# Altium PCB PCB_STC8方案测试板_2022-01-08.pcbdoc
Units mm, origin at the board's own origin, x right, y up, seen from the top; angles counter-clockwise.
Board outline 98 x 98 mm, 2 copper layers (Top Layer, Bottom Layer); 68 components, 57 nets, 265 pads, 60 vias.
Unrouted connection lines stored in the file: 3.
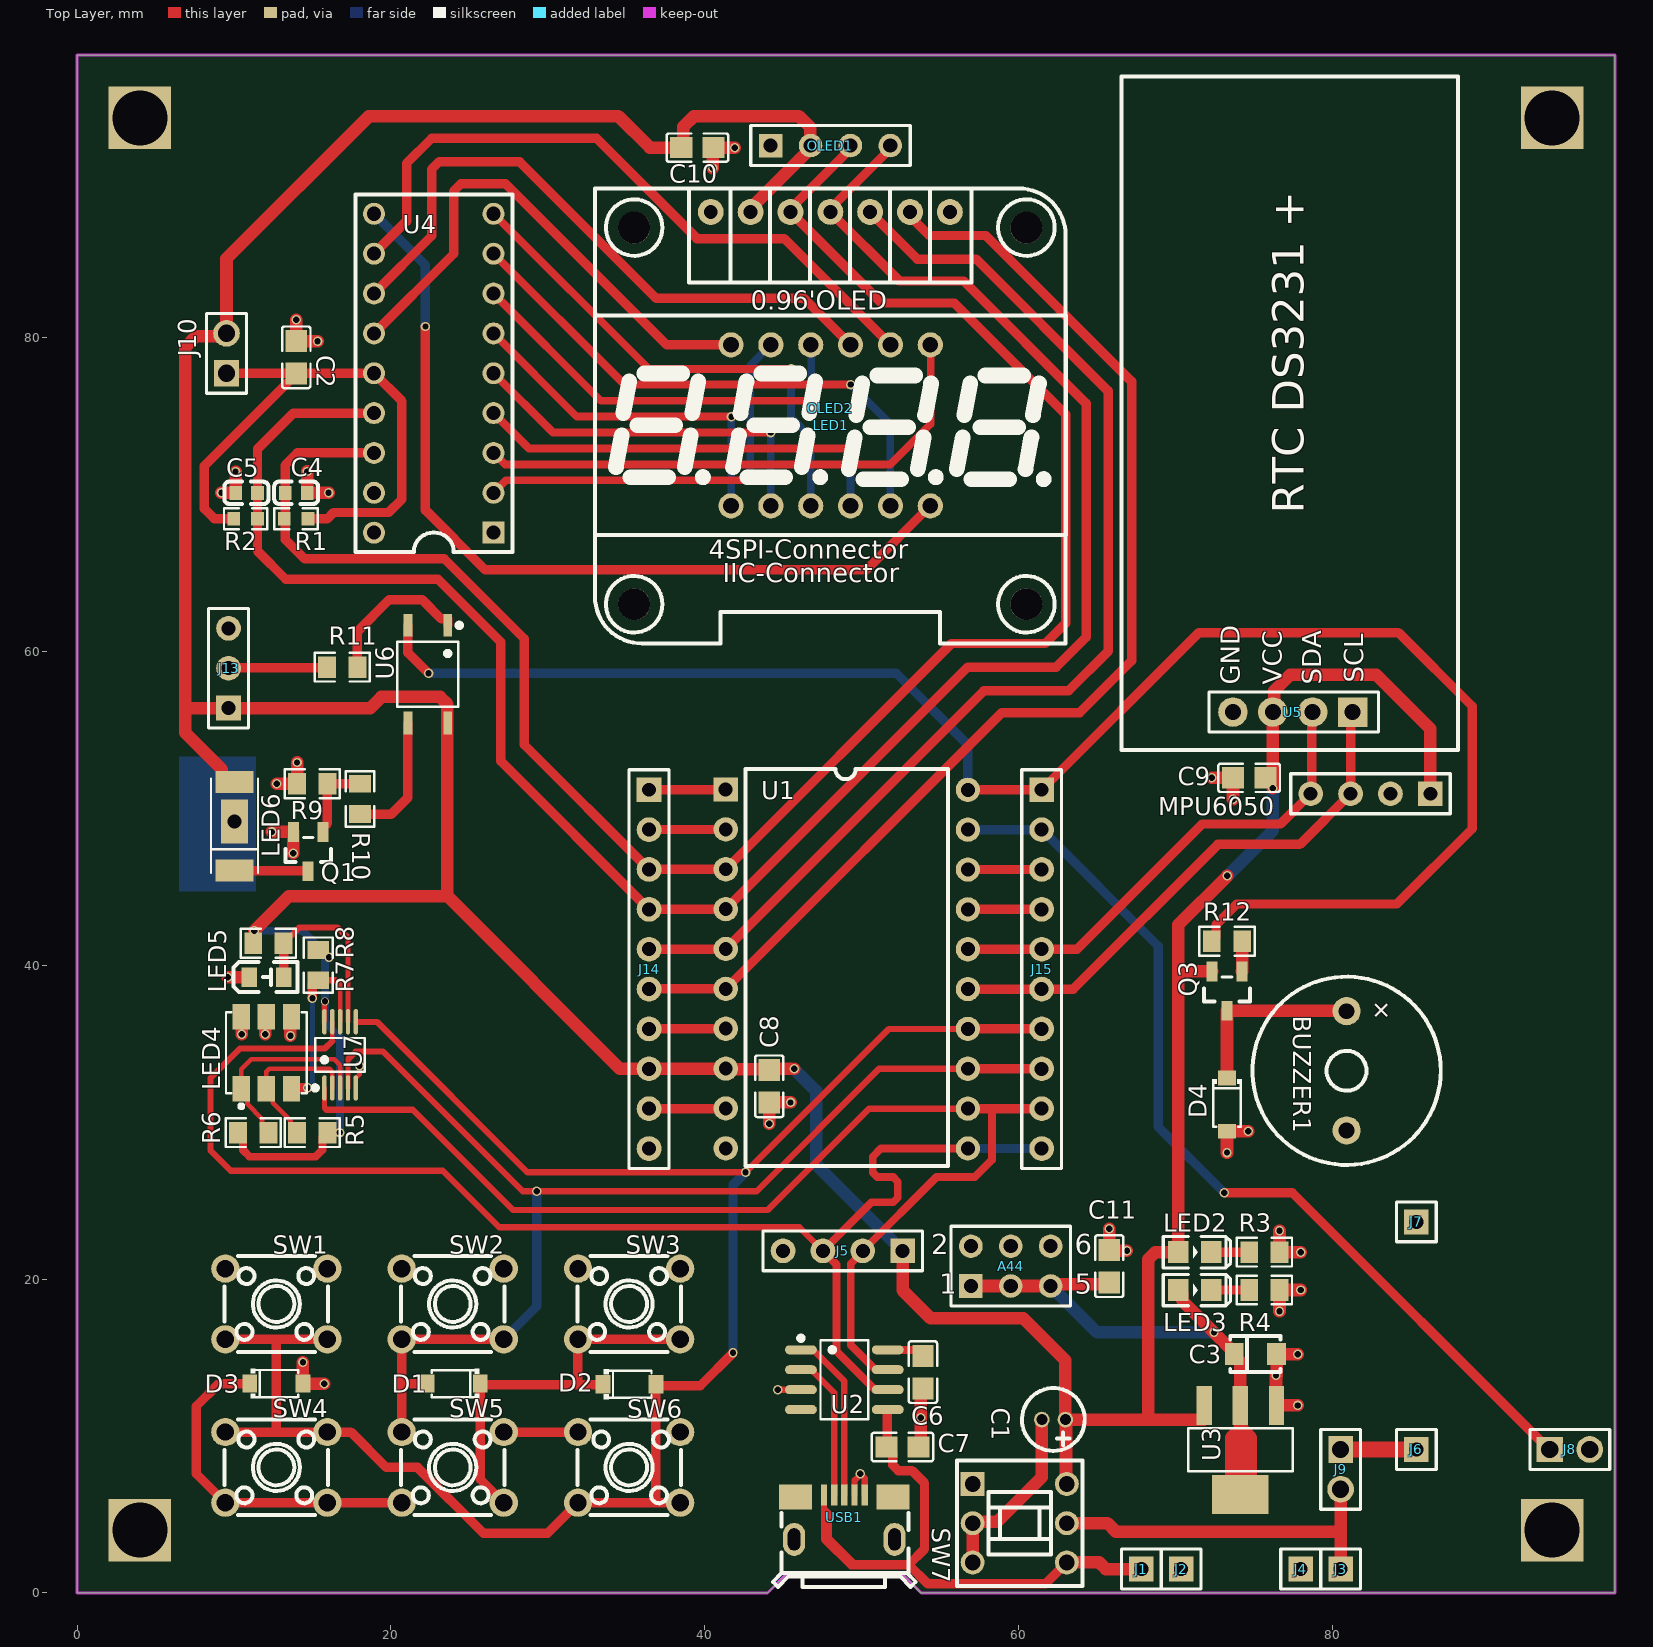
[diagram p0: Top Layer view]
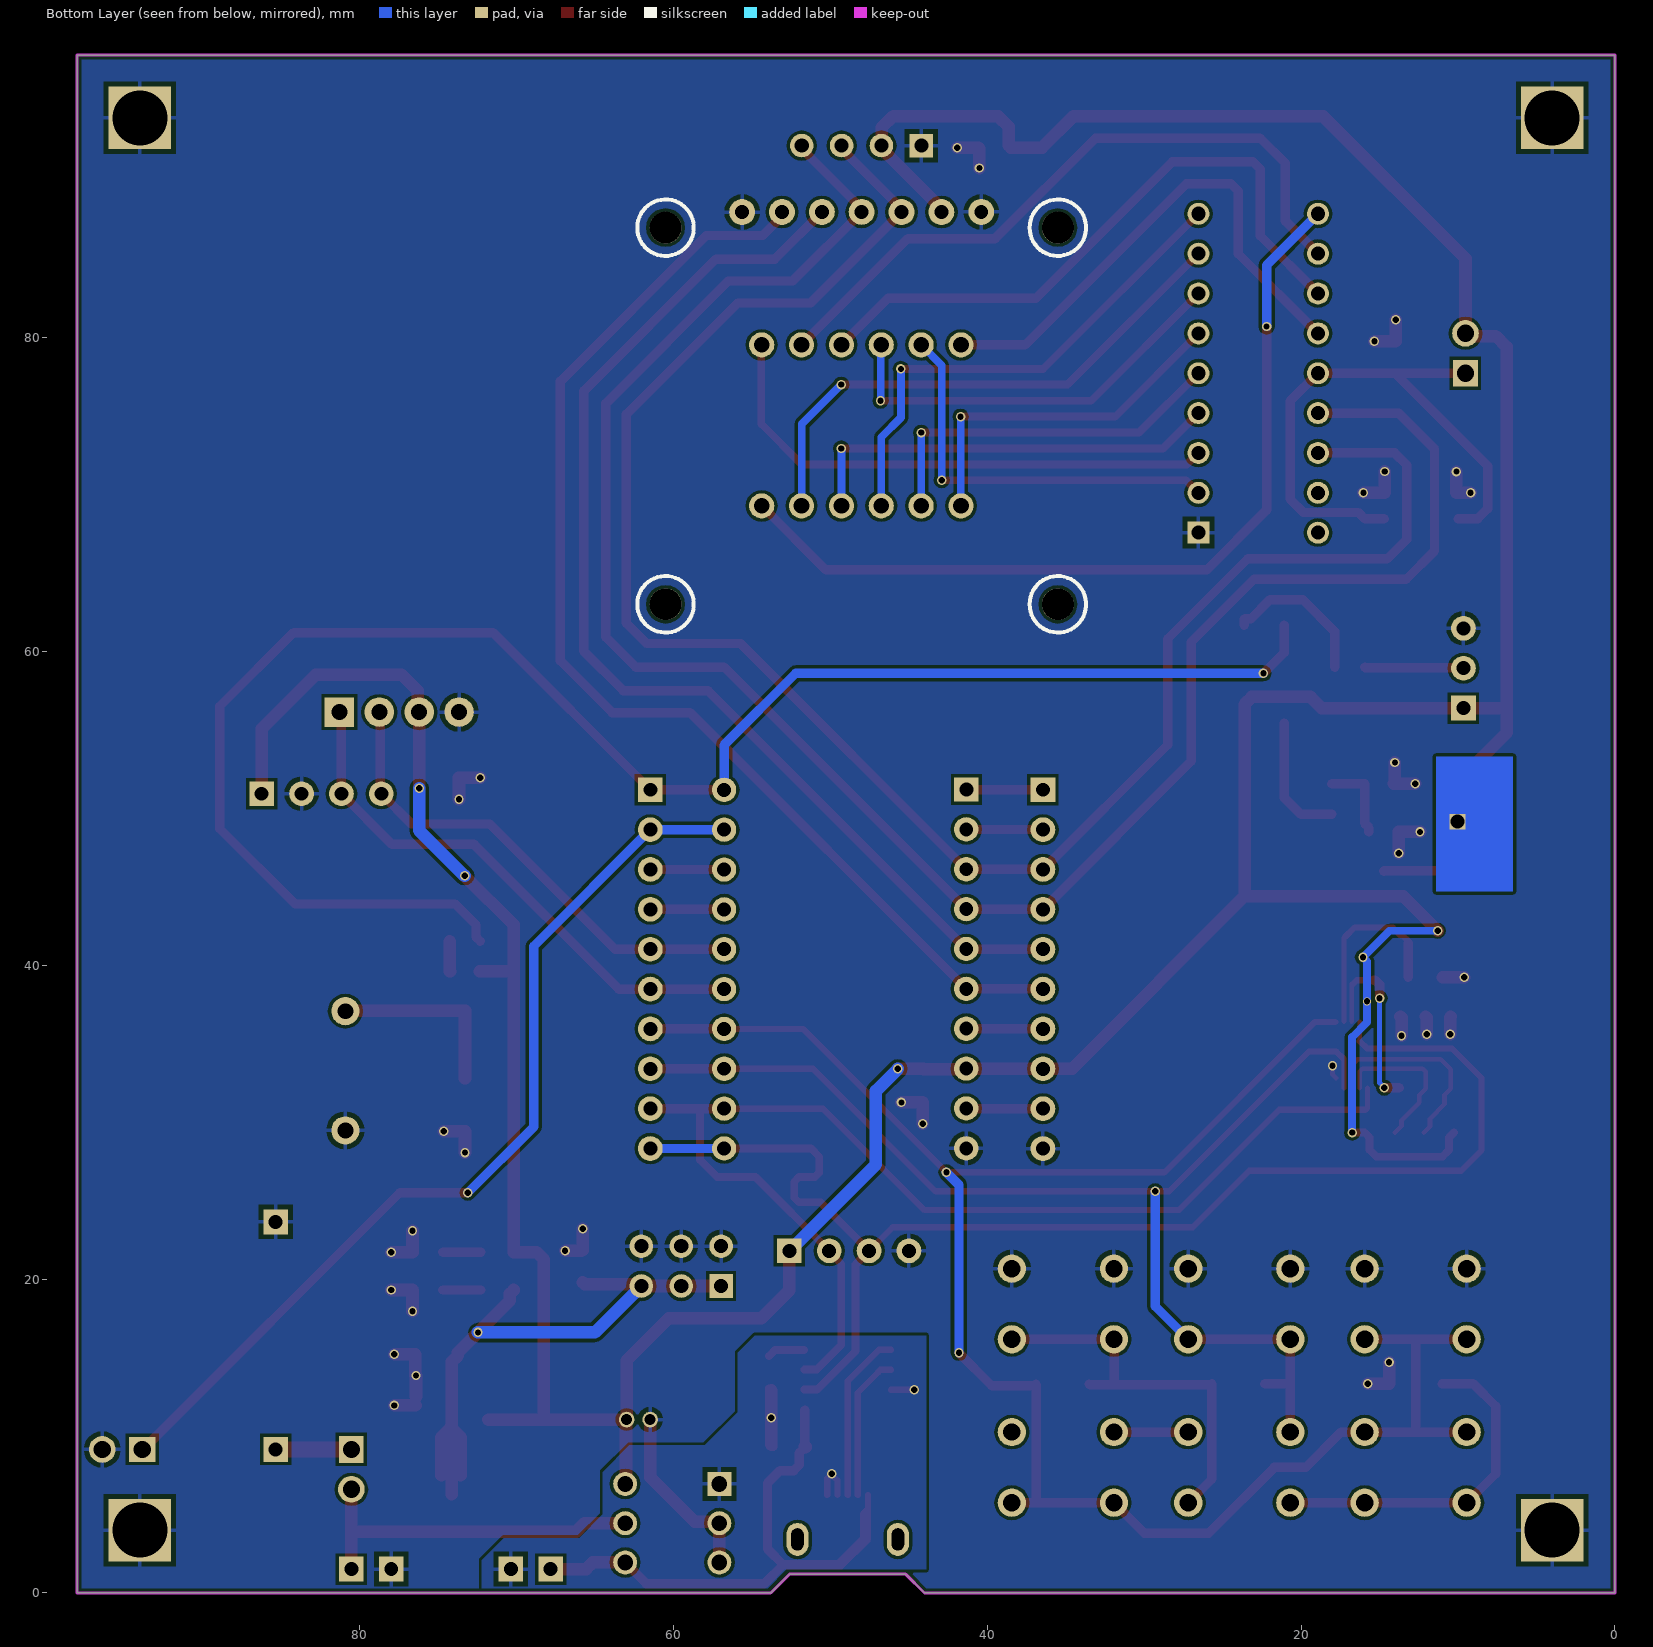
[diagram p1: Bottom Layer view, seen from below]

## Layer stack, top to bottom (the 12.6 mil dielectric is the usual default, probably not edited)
Top Solder: solder mask 0.0102, Solder Resist, Dk 3.5
Top Layer: signal copper 0.0356
Dielectric1: dielectric 0.32, FR-4, Dk 4.8
Bottom Layer: signal copper 0.0356
Bottom Solder: solder mask 0.0102, Solder Resist, Dk 3.5

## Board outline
0,0 0,98 98,98 98,0 53.8,0 52.6,1.2 45.2,1.2 44,0

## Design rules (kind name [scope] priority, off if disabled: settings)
AssemblyTestPointUsage [All] p1 off:
AssemblyTestpoint [All] p1 off: testpointundercomponent=TRUE minsize=1.016 maxsize=2.54 preferedsize=1.524 minholesize=0 maxholesize=1.016 preferedholesize=0.813 testpointgrid=0.025 usegrid=TRUE gridtolerance=0 allowsidetop=TRUE allowsidebottom=TRUE
Clearance [All] p1: gap=0.2 ignorepadtopadclearanceinfootprint=TRUE
ComponentClearance [All] p1 off: gap=0.254 collisioncheckmode=3 verticalgap=0.254 showdistances=FALSE
DiffPairsRouting [All] p1 off: maxlimit=0.254 minlimit=0.254 mostfreqgap=0.254 toplayer_minwidth=0.381 toplayer_maxwidth=0.381 toplayer_prefwidth=0.381 bottomlayer_minwidth=0.381 bottomlayer_maxwidth=0.381 bottomlayer_prefwidth=0.381 maxuncoupledlength=12.7
FabricationTestPointUsage [All] p1 off: valid=0 allowmultiple=FALSE
FabricationTestpoint [All] p1 off: side=3 testpointundercomponent=TRUE minsize=1.016 maxsize=2.54 preferedsize=1.524 minholesize=0 maxholesize=1.016 preferedholesize=0.813 testpointgrid=0.025 allowsidetop=TRUE allowsidebottom=TRUE usegrid=TRUE gridtolerance=0
FanoutControl Fanout_BGA [IsBGA] p1 off: bgadir=Out bgaviamode=Centered fanoutstyle=Auto fanoutdirection=Alternating viagrid=0.025 // Fanout_BGA (Default Rule)
FanoutControl Fanout_LCC [IsLCC] p2 off: bgadir=Out bgaviamode=Centered fanoutstyle=Auto fanoutdirection=Alternating viagrid=0.025 // Fanout_LCC (Default Rule)
FanoutControl Fanout_SOIC [IsSOIC] p3 off: bgadir=Out bgaviamode=Centered fanoutstyle=Auto fanoutdirection=Alternating viagrid=0.025 // Fanout_SOIC (Default Rule)
FanoutControl Fanout_Small [(CompPinCount < 5)] p4 off: bgadir=Out bgaviamode=Centered fanoutstyle=Auto fanoutdirection=OutThenIn viagrid=0.025 // Fanout_Small (Default Rule)
FanoutControl Fanout_Default [All] p5 off: bgadir=Out bgaviamode=Centered fanoutstyle=Auto fanoutdirection=Alternating viagrid=0.025 // Fanout_Default (Default Rule)
Height [All] p1 off: minheight=0 maxheight=25.4 prefheight=12.7
HoleSize [All] p1 off: absolutevalues=TRUE maxlimit=2.54 minlimit=0.025 maxpercent=80.000 minpercent=20.000
HoleToHoleClearance [All] p1 off: gap=0.254 allowstackedmicrovias=TRUE
LayerPairs [All] p1 off: enforce=TRUE
MinimumSolderMaskSliver [All] p1 off: minsoldermaskwidth=0.254
NetAntennae [All] p1 off: netantennaetolerance=0
PasteMaskExpansion [All] p1 off: expansion=0
PlaneClearance [All] p1 off: clearance=0.508
PlaneConnect [All] p1 off: planeconnectstyle=Relief reliefexpansion=0.508 reliefentries=4 reliefconductorwidth=0.254 reliefairgap=0.254
PolygonConnect [All] p1: thpad.connectstyle=Relief thpad.reliefconductorwidth=0.254 thpad.reliefentries=4 thpad.polygonreliefangle="90 Angle" thpad.airgapwidth=0.3 smdpad.connectstyle=Relief smdpad.reliefconductorwidth=0.254 smdpad.reliefentries=4 smdpad.polygonreliefangle="90 Angle" smdpad.airgapwidth=0.3 via.connectstyle=Direct via.reliefconductorwidth=0.254 via.reliefentries=4 via.polygonreliefangle="90 Angle" via.airgapwidth=0.3
RoutingCorners [All] p1 off: cornerstyle=45-Degree minsetback=2.54 maxsetback=2.54
RoutingLayers [All] p1 off: top layer_v5=TRUE bottom layer_v5=TRUE
RoutingPriority [All] p1 off: routingpriority=0
RoutingTopology [All] p1 off: topology=Shortest
RoutingVias [All] p1: holewidth=0.4 width=0.6 viastyle="Through Hole" minholewidth=0.4 minwidth=0.6 maxholewidth=0.4 maxwidth=0.6
ShortCircuit [All] p1 off: allowed=FALSE
SilkToSilkClearance [All] p1 off: silktosilkclearance=0.254
SilkToSolderMaskClearance [IsPad] p1 off: minsilkscreentomaskgap=0.254 clearancetoexposedcopper=TRUE
SolderMaskExpansion [All] p1 off: expansion=0.102 istentingtop=FALSE
UnRoutedNet [All] p1 off:
UnpouredPolygon [All] p1 off:
Width [All] p1: maxlimit=2.54 minlimit=0.254 preferedwidth=0.508
1 further rules are at their usual default settings.

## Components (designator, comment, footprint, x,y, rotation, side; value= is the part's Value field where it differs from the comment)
A44 "Comment" HDR2X3 56.96,19.56 r0 top
BUZZER1 "TMB12A05" BUZ-TH_BD12.0-P7.60-D0.6-FD 80.899,33.274 r270 top
C1 "10u" ?#1 62.23,11.049 r180 top
C2 "104" C0805 13.97,78.74 r270 top
C3 "10uF" CAP-SMD_L3.2-W1.6 75.085,15.216 r0 top
C4 "101" C0603 13.97,70.104 r0 top
C5 "101" C0603 10.8,70.1 r0 top
C6 "104" C0805 53.9,14.07 r270 top
C7 "104" C0805 52.6,9.3 r180 top
C8 "0.1u" C0805 44.109,32.288 r90 top
C9 "0.1u" C0805 74.69,51.943 r0 top
C10 "0.1u" C0805 39.53,92.1 r180 top
C11 "0.1u" C0805 65.775,20.82 r270 top
D1 "1N4148W-T4" SOD-123_L2.8-W1.8-LS3.7-RD 24.003,13.335 r180 top
D2 "1N4148W-T4" SOD-123_L2.8-W1.8-LS3.7-RD 35.2,13.3 r0 top
D3 "1N4148W-T4" SOD-123_L2.8-W1.8-LS3.7-RD 12.7,13.338 r0 top
D4 "1N4148W-T4" SOD-123_L2.8-W1.8-LS3.7-RD 73.279,31.115 r270 top
J1 "充电+" HDR-M-2.54_1X1 67.818,1.524 r270 top
J2 "充电-" HDR-M-2.54_1X1 70.358,1.524 r270 top
J3 "锂电池供电+" HDR-M-2.54_1X1 80.518,1.524 r270 top
J4 "锂电池供电-" HDR-M-2.54_1X1 77.978,1.524 r270 top
J5 "HDR-M-2.54_1x4" HDR-M-2.54_1X4 48.8,21.8 r180 top
J6 "led驱动+" HDR-M-2.54_1X1 85.344,9.144 r90 top
J7 "led驱动-" HDR-M-2.54_1X1 85.344,23.644 r90 top
J8 "PWM输入" HDR-M-2.54_1X2 95.123,9.144 r0 top
J9 "led驱动+" HDR-M-2.54_1X2 80.518,7.874 r270 top
J10 "HDR-M-2.54_1x2" HDR-M-2.54_1X2 9.525,78.994 r90 top
J13 "HDR-M-2.54_1x3" HDR-M-2.54_1X3 9.652,58.928 r90 top
J14 "HDR-M-2.54_1x10" HDR-M-2.54_1X10 36.449,39.751 r270 top
J15 "HDR-M-2.54_1x10" HDR-M-2.54_1X10 61.468,39.751 r270 top
LED1 "SR410361N" LED-SEG-TH_12P-L30.0-W14.0-P2.54-S10.26-BL 48.022,74.404 r0 top
LED2 "LED-0805_G" LED0805_GREEN 71.213,21.717 r0 top
LED3 "LED-0805_G" LED0805_GREEN 71.213,19.304 r0 top
LED4 "5050-RGB" LED-ARRAY-SMD_6P-L5.4-W5.0-TL-FD 12.065,34.417 r90 top
LED5 "0805Y" LED0805-RD_YELLOW 12.065,39.243 r0 top
LED6 "HL-A-5730D34W_C210350" LED-SMD_3P-L5.7-W3.0-RD 10.033,48.849 r90 top
MPU6050 "MCU6050" HDR-M-2.54_1X4 82.423,50.927 r180 top (schematic designator J12)
OLED1 "0.96OLED_4P" HDR1X4 44.2,92.234 r0 top
OLED2 "0.96OLED_7P" 0.96OLED_7P 48,88 r0 top
Q1 "s8050" SOT-23-3_L2.9-W1.3-P1.90-LS2.4-TR 14.732,47.244 r90 top
Q3 "s8550" SOT-23-3_L2.9-W1.6-P1.90-LS2.8-TR-CW 73.279,38.354 r90 top
R1 "10k" R0603 13.961,68.453 r0 top
R2 "10k" R0603 10.747,68.449 r180 top
R3 "1k" R0805 75.658,21.717 r0 top
R4 "680" R0805 75.658,19.304 r0 top
R5 "1k" R0805 14.986,29.337 r180 top
R6 "1k" R0805 11.226,29.337 r180 top
R7 "1k" R0805 15.367,40.005 r90 top
R8 "1k" R0805 12.192,41.402 r180 top
R9 "47k" R0805 14.986,51.562 r0 top
R10 "4k7" R0805 18.034,50.596 r90 top
R11 "1k" R0805 16.9,59 r180 top
R12 "2k" R0805 73.279,41.529 r0 top
SW1 "K2-1102DP-C4SW-04" KEY-TH_4P-L6.0-W6.0-P4.50-LS6.5 12.7,18.415 r0 top
SW2 "K2-1102DP-C4SW-04" KEY-TH_4P-L6.0-W6.0-P4.50-LS6.5 23.939,18.415 r0 top
SW3 "K2-1102DP-C4SW-04" KEY-TH_4P-L6.0-W6.0-P4.50-LS6.5 35.179,18.415 r0 top
SW4 "K2-1102DP-C4SW-04" KEY-TH_4P-L6.0-W6.0-P4.50-LS6.5 12.7,8.001 r0 top
SW5 "K2-1102DP-C4SW-04" KEY-TH_4P-L6.0-W6.0-P4.50-LS6.5 23.939,8.001 r0 top
SW6 "K2-1102DP-C4SW-04" KEY-TH_4P-L6.0-W6.0-P4.50-LS6.5 35.179,8.001 r180 top
SW7 "电源开关" SW-TH_6P-L8.0-W8.0-P2.50 60.071,4.445 r270 top
U1 "STC8G1K17-38I-TSSOP20" DIP-20-wide 41.332,51.199 r0 top
U2 "CH340N" SOP-8_L5.0-W4.0-P1.27-LS6.0-BL 48.895,13.589 r270 top
U3 "AMS1117-3.3" SOT-223-4_L6.5-W3.5-P2.30-LS7.0-BR 74.131,9.117 r90 top
U4 "TM1636" DIP18-2.54-22.8X7.62MM 22.733,77.724 r90 top
U5 "DS3231模块" ?#2 76.962,73.914 r90 top
U6 "TLP184(GB-TPL,SE(T" SOP-4_L3.7-W4.6-P2.54-LS7.0-BR 22.352,58.547 r90 top
U7 "CH442E" MSOP-10_L3.0-W3.0-P0.50-LS5.0-BL 16.764,34.29 r0 top
USB1 "U254-051T-4BH82-S2S" MICRO-USB-SMD_U254-051T-4BH82-S2S 48.895,4.826 r0 top

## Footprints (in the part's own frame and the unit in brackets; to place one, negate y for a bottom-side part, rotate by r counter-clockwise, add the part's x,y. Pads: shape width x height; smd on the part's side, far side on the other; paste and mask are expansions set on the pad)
0.96OLED_7P [mm]
  round 1.65 hole 0.89: 1(-7.619,0.001) 2(-5.079,-0.004) 3(-2.539,-0.004) 4(0.001,0.004) 5(2.539,-0.001) 6(5.079,-0.001) 7(7.619,-0.004)
  round 2.032 hole 2.032 unplated: ""(-12.501,-24.997) ""(-12.501,-0.997) ""(12.498,-24.997) ""(12.498,-0.997)
  silkscreen extent -15,-27.5 15,1.5
BUZ-TH_BD12.0-P7.60-D0.6-FD [mm]
  round 1.8 hole 1: 1(-3.8,0) 2(3.8,0)
  silkscreen extent -6,-6 6,6
C0603 [mm]
  rect 0.8x0.9 smd: 1(-0.7,0) 2(0.7,0)
  silkscreen extent -1.41,-0.71 1.39,0.72
C0805 [mm]
  rect 1.41x1.35 smd: 1(-1.03,0) 2(1.03,0)
  silkscreen extent -1.96,-0.9 1.96,0.9
CAP-SMD_L3.2-W1.6 [mm]
  rect 1.2x1.4 smd: 1(-1.35,0) 2(1.35,0)
  silkscreen extent -1.6,-1.14 1.6,1.14
DIP18-2.54-22.8X7.62MM [mm]
  rect 1.4x1.4 hole 0.899: 1(-10.16,-3.81)
  round 1.4 hole 0.899: 2(-7.62,-3.81) 3(-5.08,-3.81) 4(-2.54,-3.81) 5(0,-3.81) 6(2.54,-3.81) 7(5.08,-3.81) 8(7.62,-3.81) 9(10.16,-3.81) 10(10.16,3.81) 11(7.62,3.81) 12(5.08,3.81) 13(2.54,3.81) 14(0,3.81) 15(-2.54,3.81) 16(-5.08,3.81) 17(-7.62,3.81) 18(-10.16,3.81)
  silkscreen extent -11.38,-5 11.38,5
DIP-20-wide [mil] "STC8G1K17-38I-TSSOP20"
  rect 61x61 hole 35: 1(0,0)
  round 61 hole 35: 2(0.25,-100.02) 3(0.25,-200.04) 4(0.25,-300.06) 5(0.25,-400.08) 6(0.25,-500.1) 7(0.25,-600.12) 8(0.25,-700.14) 9(0.25,-800.16) 10(0.25,-900.18) 11(607.75,-900.59) 12(607.75,-800.62) 13(607.75,-700.64) 14(607.75,-600.66) 15(607.75,-500.68) 16(607.75,-400.7) 17(607.75,-300.73) 18(607.75,-200.75) 19(607.75,-100.77) 20(607.75,-0.79)
  silkscreen extent 50,-945 558,51
HDR1X4 [mm] "Connector; Header; 4 Position"
  rect 1.5x1.5 hole 0.9: 1(0,0)
  round 1.5 hole 0.9: 2(2.54,0) 3(5.08,0) 4(7.62,0)
  silkscreen extent -1.27,-1.27 8.89,1.27
HDR2X3 [mm] "Connector; Header; 3x2 Position"
  rect 1.5x1.5 hole 0.9: 1(0,0)
  round 1.5 hole 0.9: 2(0,2.54) 3(2.54,0) 4(2.54,2.54) 5(5.08,0) 6(5.08,2.54)
  silkscreen extent -1.27,-1.27 6.35,3.81, body extent -1.27,-1.27 6.35,3.81, height 8.54
HDR-M-2.54_1X1 [mil]
  rect 62x62 hole 35: 1(0,0)
  silkscreen extent -50,-50 50,50
HDR-M-2.54_1X2 [mm]
  rect 1.7x1.575 hole 1.1: 1(-1.27,0)
  round 1.7 hole 1.1: 2(1.27,0)
  silkscreen extent -2.54,-1.27 2.54,1.27
HDR-M-2.54_1X3 [mil]
  rect 62x62 hole 35: 1(-100,0)
  round 62 hole 35: 2(0,0) 3(100,0)
  silkscreen extent -150,-50 150,50
HDR-M-2.54_1X4 [mil]
  rect 62x62 hole 35: 1(-150,0)
  round 62 hole 35: 2(-50,0) 3(50,0) 4(150,0)
  silkscreen extent -200,-50 200,50
HDR-M-2.54_1X10 [mil]
  rect 62x62 hole 35: 1(-450,0)
  round 62 hole 35: 2(-350,0) 3(-250,0) 4(-150,0) 5(-50,0) 6(50,0) 7(150,0) 8(250,0) 9(350,0) 10(450,0)
  silkscreen extent -500,-50 500,50
KEY-TH_4P-L6.0-W6.0-P4.50-LS6.5 [mm]
  round 1.8 hole 1.1: 1(-3.251,-2.25) 2(3.251,-2.25) 3(3.251,2.25) 4(-3.251,2.25)
  silkscreen extent -3.3,-3.05 3.3,3.05
LED0805-RD_YELLOW [mm]
  rect 1x1.25 smd: 1(-1.1,0) 2(1.1,0)
  silkscreen extent -2.1,-0.95 1.98,0.96
LED0805_GREEN [mm]
  rect 1.3x1.4 smd: 1(-1.05,0) 2(1.05,0)
  silkscreen extent -2,-1 2.3,1
LED-ARRAY-SMD_6P-L5.4-W5.0-TL-FD [mm]
  rect 1.625x1.1 smd: 1(-2.287,1.6) 2(-2.287,0) 3(-2.287,-1.6) 4(2.287,-1.6) 5(2.287,0) 6(2.287,1.6)
  silkscreen extent -3.52,-2.58 2.58,2.58
LED-SEG-TH_12P-L30.0-W14.0-P2.54-S10.26-BL [mm]
  round 1.6 hole 1: 1(-6.35,-5.13) 2(-3.81,-5.13) 3(-1.27,-5.13) 4(1.27,-5.13) 5(3.81,-5.13) 6(6.35,-5.13) 7(6.35,5.13) 8(3.81,5.13) 9(1.27,5.13) 10(-1.27,5.13) 11(-3.81,5.13) 12(-6.35,5.13)
  silkscreen extent -15,-7 15,7
LED-SMD_3P-L5.7-W3.0-RD [mm]
  rect 1.4x2.4 smd: 1(-2.82,0) 2(2.82,0)
  rect 2.8x1.7 smd: 3(0.3,0)
  silkscreen extent -2.96,-1.5 3.04,1.5
MICRO-USB-SMD_U254-051T-4BH82-S2S [mm]
  rect 0.4x1.35 smd: 1(-1.3,1.413) 2(-0.65,1.413) 3(0,1.413) 4(0.65,1.413) 5(1.3,1.413)
  rect 2.1x1.6 smd: 6(3.1,1.288) 9(-3.1,1.288)
  oval 1.4x2.1 hole 0.8 slot 1.4 at 90 deg: 7(3.2,-1.412) 8(-3.2,-1.412)
  silkscreen extent -4.55,-4.44 4.55,0.26
MSOP-10_L3.0-W3.0-P0.50-LS5.0-BL [mm]
  oval 0.28x1.62 smd: 1(-1,-2.11) 2(-0.5,-2.11) 3(0,-2.11) 4(0.5,-2.11) 5(1,-2.11) 6(1,2.11) 7(0.5,2.11) 8(0,2.11) 9(-0.5,2.11) 10(-1,2.11)
  silkscreen extent -1.74,-2.26 1.58,1.07
R0603 [mm]
  rect 0.806x0.864 smd: 1(-0.753,0) 2(0.753,0)
  silkscreen extent -1.39,-0.66 1.39,0.66
R0805 [mm]
  rect 1.133x1.377 smd: 1(-0.966,0) 2(0.966,0)
  silkscreen extent -1.76,-0.92 1.76,0.92
SOD-123_L2.8-W1.8-LS3.7-RD [mm]
  rect 0.95x1.15 smd: 1(-1.693,0) 2(1.693,0)
  silkscreen extent -1.63,-0.94 1.41,0.94
SOP-4_L3.7-W4.6-P2.54-LS7.0-BR [mm]
  rect 1.447x0.56 smd: 1(3.11,-1.27) 3(3.11,1.27) 4(-3.11,1.27) 6(-3.11,-1.27)
  silkscreen extent -2.07,-2.15 3.26,1.95
SOP-8_L5.0-W4.0-P1.27-LS6.0-BL [mm]
  oval 0.574x2.036 smd: 1(-1.905,-2.768) 2(-0.635,-2.768) 3(0.635,-2.768) 4(1.905,-2.768) 5(1.905,2.768) 6(0.635,2.768) 7(-0.635,2.768) 8(-1.905,2.768)
  silkscreen extent -2.79,-2.92 2.53,1.52
SOT-23-3_L2.9-W1.3-P1.90-LS2.4-TR [mm]
  rect 1.25x0.7 smd: 1(1.25,0.95) 2(1.25,-0.95) 3(-1.25,0)
  silkscreen extent -0.65,-1.46 0.9,1.46
SOT-23-3_L2.9-W1.6-P1.90-LS2.8-TR-CW [mm]
  rect 1.25x0.7 smd: 1(1.25,0.95) 2(1.25,-0.95) 3(-1.25,0)
  silkscreen extent -0.65,-1.46 0.9,1.46
SOT-223-4_L6.5-W3.5-P2.30-LS7.0-BR [mm]
  rect 2.47x0.98 smd: 1(2.835,-2.3) 2(2.835,0) 3(2.835,2.3)
  rect 2.47x3.6 smd: 4(-2.835,0)
  silkscreen extent -1.37,-3.33 1.37,3.33
SW-TH_6P-L8.0-W8.0-P2.50 [mm]
  rect 1.524x1.524 hole 1: 1(-2.5,-3)
  round 1.524 hole 1: 2(0,-3) 3(2.5,-3) 4(-2.5,3) 5(0,3) 6(2.5,3)
  silkscreen extent -4,-4 4,4
?#1 [mm]
  round 1 hole 0.7: 1(-0.751,0) 2(0.751,0)
  silkscreen extent -1.98,-2 2.01,2
?#2 [mm] "Connector; Header; 4 Position"
  rect 1.88x1.88 hole 1.016: 1(-17.78,-4.318)
  round 1.88 hole 1.016: 2(-17.78,-1.778) 3(-17.78,0.762) 4(-17.78,3.302)
  silkscreen extent -20.19,-11.05 22.73,10.41

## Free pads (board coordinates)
  rect 4x4 hole 3.5: ""(4,4) ""(4,94) ""(94,4) ""(94,94)
  rect 1x1 hole 0.9: ""(10.033,49.149)

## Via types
v1: diameter 0.6, hole 0.4, Top Layer to Bottom Layer, 59 vias
v2: diameter 0.5, hole 0.4, Top Layer to Bottom Layer, 1 vias

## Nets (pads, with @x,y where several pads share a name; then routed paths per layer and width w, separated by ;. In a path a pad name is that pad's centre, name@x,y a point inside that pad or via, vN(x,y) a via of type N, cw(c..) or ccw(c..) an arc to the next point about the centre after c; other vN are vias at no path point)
3.3V: A44.1 A44.3 A44.5 C3.1 C11.2 LED3.1 U3.2 U3.4 | length 41.9
  Top Layer w0.8: A44.1 A44.3 A44.5 62.155,19.675 65.66,19.675 C11.2 ; LED3.1 70.413,19.054 70.413,18.638 73.735,15.316 C3.1 73.735,15.116 74.131,14.72 U3.2 74.131,10.569 ; U3.4@73.543,7.5 73.543,9.9 74.212,10.569 ; U3.4 74.131,10.569 ; U3.4@74.8,7.5 74.8,9.9 74.131,10.569
  Bottom Layer w0.8: A44.5 65,16.6 v1(72.451,16.6)
5V: J3.1 J9.2 SW7.5 | length 22.7
  Top Layer w0.8: SW7.5 65.655,4.445 66.2,3.9 80.5,3.9 ; J3.1 J9.2
6050/RTC_SCL: J15.6 MPU6050.3 U1.15 U5.1 | length 34.8
  Top Layer w0.6: U1.15 J15.6 63.481,38.481 72.7,47.7 77.926,47.7 MPU6050.3 81.153,56.007 U5.1
6050/RTC_SDA: J15.5 MPU6050.4 U1.16 U5.2 | length 31.2
  Top Layer w0.6: U1.16 J15.5 63.721,41.021 71.7,49 76.686,49 MPU6050.4 78.676,50.991 78.676,56.07 U5.2
A: LED1.11 U4.2 | length 25.9
  Top Layer w0.5: U4.2 27.339,70.9 v1(42.9,70.9)
  Bottom Layer w0.5: v1(42.9,70.9) 42.9,78.222 LED1.11
B: LED1.7 U4.3 | length 34.3
  Top Layer w0.5: U4.3 26.556,72.644 27.286,71.914 51.814,71.914 54.4,74.5 54.4,79.506 LED1.7
BGND: C6.2 C7.1 J2.1 SW7.1 U2.3 USB1.4 USB1.5 | length 8.4
  Top Layer w0.4: v1(44.646,12.954) U2.3 ; USB1.4 49.545,7.191 49.9,7.546 v1(49.9,7.6) 50.195,7.305 USB1.5
  Top Layer w0.5: C7.1 C7.1@53.765,9.435 ; C6.2@53.765,12.905 C6.2
  Top Layer w0.8: C7.1@53.765,9.435 C6.2@53.765,12.905
  Bottom Layer w0.4: v1@44.6,13 v1(44.646,12.954)
  other v1: 53.765,11.17
BUZZER1_1: BUZZER1.1 D4.1 Q3.3 | length 11.9
  Top Layer w0.8: D4.1 Q3.3 73.294,37.089 80.884,37.089 BUZZER1.1
C: LED1.4 U4.4 | length 27.4
  Top Layer w0.5: U4.4 28.798,72.929 v1(49.3,72.929)
  Bottom Layer w0.5: LED1.4 49.3,69.282 49.296,69.286 49.296,72.925 v1(49.3,72.929)
C2_2: C2.2 J10.1 R1.2 R2.2 U4.14 | length 37.8
  Top Layer w0.6: J10.1 9.532,77.717 13.963,77.717 C2.2 13.977,77.717 18.916,77.717 U4.14 20.7,75.947 20.7,69.7 19.85,68.85 16.35,68.85 15.953,68.453 R1.2 ; R2.2 8.751,68.449 8.1,69.1 8.1,71.81 C2.2@13.954,77.664
D: LED1.2 U4.5 | length 23.9
  Top Layer w0.5: U4.5 30.324,73.943 v1(44.2,73.943)
  Bottom Layer w0.5: v1(44.2,73.943) 44.206,73.937 44.206,69.292 44.2,69.286 LED1.2
D+: U2.1 USB1.3 | length 10.9
  Top Layer w0.4: U2.1 46.905,15.494 46.992,15.407 48.895,13.505 USB1.3
D-: U2.2 USB1.2 | length 9.3
  Top Layer w0.4: U2.2 46.811,14.224 46.945,14.09 46.945,14.055 48.245,12.755 USB1.2
DP: LED1.3 U4.9 | length 32.3
  Top Layer w0.5: U4.9 36.427,78 v1(45.5,78)
  Bottom Layer w0.5: v1(45.5,78) 45.5,74.9 46.752,73.648 46.752,69.37 46.8,69.322 LED1.3
E: LED1.1 U4.6 | length 23.1
  Top Layer w0.5: U4.6 31.85,74.957 v1(41.7,74.957)
  Bottom Layer w0.5: LED1.1 41.7,69.302 41.686,69.316 41.686,74.943 v1(41.7,74.957)
F: LED1.10 U4.7 | length 26.7
  Top Layer w0.5: U4.7 33.376,75.971 v1(46.8,75.971)
  Bottom Layer w0.5: LED1.10 46.8,79.486 46.781,79.467 46.781,75.991 v1(46.8,75.971)
G: LED1.5 U4.8 | length 35
  Top Layer w0.5: U4.8 34.887,77 v1(49.3,77)
  Bottom Layer w0.5: v1(49.3,77) 51.816,74.484 51.816,69.322 51.8,69.306 LED1.5
G1: LED1.12 U4.13 | length 33.3
  Top Layer w0.6: U4.13 24,85.341 24,89.331 24.469,89.8 27.3,89.8 37.566,79.534 LED1.12
G2: LED1.9 U4.12 | length 41.2
  Top Layer w0.6: U4.12 22.6,86.481 22.6,90.731 23.069,91.2 28.2,91.2 36.9,82.5 46.326,82.5 LED1.9
G3: LED1.8 U4.11 | length 43.6
  Top Layer w0.6: U4.11 21,87.421 21,91.1 22.6,92.7 33.1,92.7 39.5,86.3 45.066,86.3 LED1.8
G4: LED1.6 U4.10 | length 55.7
  Top Layer w0.6: v1(22.2,80.7) 22.2,69 26,65.2 50.298,65.2 LED1.6
  Bottom Layer w0.6: U4.10 22.2,84.607 v1(22.2,80.7)
GND: A44.2 A44.4 A44.6 BUZZER1.2 C1.2 C2.1 C3.2 C4.2 C5.1 C8.1 C9.1 C10.1 C11.1 D3.2 D4.2 J4.1 J5.4 J7.1 J8.2 J13.3 J14.10 LED4.4 LED4.5 LED4.6 LED5.1 MPU6050.2 OLED1.1 OLED2.1 OLED2.7 pad.@4,4 pad.@4,94 pad.@94,4 pad.@94,94 Q1.1 R3.2 R4.2 R9.1 SW1.3 SW1.4 SW2.3 SW2.4 SW3.3 SW3.4 SW7.2 SW7.3 U1.10 U3.1 U4.1 U5.4 U7.5 | length 57.6
  Top Layer w0.3: U7.5@17.776,32.815 18,33.039 v1(18,33.6)
  Top Layer w0.8: v1(9.2,70.1) C5.1 v1(10.1,71.459) ; v1(9.606,39.243) LED5.1 ; LED4.6 10.5,36.67 v1(10.5,35.6) ; v1(12,35.6) 12,36.639 LED4.5 ; v1(12.423,48.494) Q1.1 v1(13.782,47.135) ; v1(12.732,51.567) R9.1@14.02,51.567 ; v1(13.6,35.5) 13.6,36.64 LED4.4 ; v1(13.97,81.129) C2.1 v1(15.329,79.77) ; R9.1 R9.1@14.02,51.567 ; v1(14.02,52.921) R9.1@14.02,51.567 ; R9.1@14.091,51.567 R9.1@14.02,51.567 ; v1(14.393,14.697) D3.2 v1(15.752,13.338) ; v1(14.67,71.463) C4.2 v1(16.029,70.104) ; v1(40.5,90.8) 40.5,92.04 C10.1 v1(41.919,92.1) ; v1(44.109,29.899) C8.1 v1(45.468,31.258) ; SW7.3 SW7.2 57.159,4.533 58.633,4.533 61.479,7.379 C1.2 ; v1(65.775,23.209) C11.1 65.825,21.8 v1(66.9,21.8) ; v1(72.301,51.943) C9.1 v1(73.66,50.584) ; v1(73.279,28.063) D4.2 v1(74.638,29.422) ; U3.1@76.4,12.5 v1(76.4,13.859) ; U3.1 v1(77.79,11.952) ; v1@76.435,13.857 C3.2 v1(77.794,15.216) ; v1(76.624,17.945) R4.2 v1(77.983,19.304) ; v1(76.624,23.076) R3.2 v1(77.983,21.717)
J9_1: J6.1 J9.1 | length 4.8
  Top Layer w1: J9.1 J6.1
J13_2: J13.2 R11.2 | length 6.3
  Top Layer w0.6: J13.2 9.688,58.964 15.898,58.964 R11.2
KEY0: D1.2 J15.8 SW2.1 SW2.2 SW5.3 SW5.4 SW6.1 SW6.2 U1.13 U7.4 | length 82.3
  Top Layer w0.3: U7.4 17.264,34.011 17.3,34.047
  Top Layer w0.4: 17.3,34.047 17.753,34.5 19.5,34.5 28.4,25.6 43.3,25.6 51.103,33.403 U1.13
  Top Layer w0.6: SW5.4 20.688,13.208 ; D1.2 20.815,13.335 20.688,13.208 ; SW5.3 SW6.2 ; SW2.2 SW2.1 20.688,13.208 ; U1.13@56.77,33.402 J15.8
  Bottom Layer w0.6: SW2.2 29.3,18.274 v1(29.3,25.6)
KEY1: D2.2 J15.7 SW1.1 SW1.2 SW4.3 SW4.4 SW6.3 SW6.4 U1.14 U7.6 | length 121.2
  Top Layer w0.4: U7.6@17.818,36.388 19.112,36.388 28.7,26.8 v1(42.6,26.8) ; v1@42.75,26.95 51.742,35.942 U1.14
  Top Layer w0.6: SW4.4 12.7,10.251 ; SW1.1 12.7,16.165 ; SW1.2 12.7,16.165 ; D2.2@36.893,13.208 39.708,13.208 v1(41.8,15.3) ; D2.2 36.872,13.279 36.872,5.751 ; SW6.4 36.872,5.751 ; U1.14 J15.7 ; 12.7,10.251 SW4.3 17.449,10.251 19.7,8 21.7,8 25.9,3.8 29.977,3.8 SW6.3 36.872,5.751 ; 12.7,10.251 12.7,16.165
  Bottom Layer w0.6: v1(41.8,15.3) 41.8,26 v1(42.6,26.8)
LED2_2: LED2.2 R3.1 | length 2.4
  Top Layer w0.6: LED2.2 R3.1
LED3_2: LED3.2 R4.1 | length 2.4
  Top Layer w0.6: LED3.2 R4.1
LGND: LED6.3 pad.@10.033,49.149
null: 
OLED_DC: J14.6 OLED2.6 U1.6 | length 76
  Top Layer w0.6: J14.6 36.457,38.489 41.331,38.489 U1.6 58.942,56.1 63.9,56.1 67.2,59.4 67.2,77.2 57.9,86.5 54.3,86.5 53.079,87.721 OLED2.6
OLED_RES: J14.5 OLED2.5 U1.5 | length 73.6
  Top Layer w0.6: J14.5 36.457,41.029 41.331,41.029 U1.5 57.787,57.485 63.185,57.485 65.7,60 65.7,76.6 57.3,85 53.537,85 OLED2.5
OLED_SCL: C4.1 J14.3 OLED1.3 OLED2.3 R1.1 U1.3 U4.16 | length 121.6
  Top Layer w0.6: U4.16 14.044,72.644 13.27,71.87 C4.1 13.27,68.453 13.27,67.13 14.5,65.9 23.4,65.9 28.5,60.8 28.5,54.05 J14.3 36.457,46.109 41.33,46.109 U1.3 55.721,60.5 61.7,60.5 63,61.8 63,75.1 55.9,82.2 51.257,82.2 OLED2.3 45.461,88.206 49.28,92.024 OLED1.3
OLED_SDA: C5.2 J14.4 OLED1.4 OLED2.4 R2.1 U1.4 U4.15 | length 130.8
  Top Layer w0.6: U4.15 13.784,75.184 11.5,72.9 C5.2 R2.1 11.5,66.4 13.3,64.6 23,64.6 27,60.6 27,53.01 J14.4 36.457,43.569 41.33,43.569 U1.4 56.761,59 62.4,59 64.3,60.9 64.3,75.8 56.5,83.6 52.405,83.6 OLED2.4 48.001,88.21 51.82,92.028 OLED1.4
P1.2: J14.1 U1.1 | length 4.9
  Top Layer w0.6: J14.1 36.458,51.19 41.323,51.19 U1.1
P1.3: J14.2 U1.2 | length 4.9
  Top Layer w0.6: J14.2 36.458,48.65 41.33,48.65 U1.2
P3.6: J15.4 U1.17 | length 4.7
  Top Layer w0.6: U1.17 J15.4
P3.7: J15.3 U1.18 | length 4.7
  Top Layer w0.6: U1.18 J15.3
P55/VREF: J14.9 U1.9 | length 4.9
  Top Layer w0.6: J14.9 36.456,30.868 41.332,30.868 U1.9
PWM0: J8.1 J15.2 U1.19 | length 60.2
  Top Layer w0.6: v1(73.1,25.5) 77.434,25.5 93.79,9.144 J8.1
  Bottom Layer w0.6: U1.19@56.77,48.64 J15.2 ; J15.2 68.9,41.209 68.9,29.7 v1(73.1,25.5)
PWM1: J15.1 R12.1 U1.20 U6.3 | length 108.8
  Top Layer w0.6: U6.3 21.082,59.918 v1(22.4,58.6) ; U1.20 56.77,51.18 J15.1 J15.1 71.487,61.2 84.2,61.2 88.9,56.5 88.9,48.7 84.1,43.9 73.9,43.9 72.579,42.579 72.579,41.795 R12.1
  Bottom Layer w0.6: v1(22.4,58.6) 52.2,58.6 56.769,54.031 U1.20
Q1_2: Q1.2 R9.2 R10.2 | length 5.3
  Top Layer w0.6: Q1.2 15.682,48.769 15.952,49.039 R9.2 R10.2
Q1_3: LED6.1 Q1.3 | length 4.7
  Top Layer w0.6: LED6.1 10.05,46.012 14.715,46.012 Q1.3
R: J5.3 J15.10 U1.11 U2.6 U7.9 | length 88.3
  Top Layer w0.3: 16.264,35.164 U7.9
  Top Layer w0.4: 16.264,35.164 15.8,34.7 10.4,34.7 8.5,32.8 8.5,28.2 9.8,26.9 23.3,26.9 26.9,23.3 46.03,23.3 J5.3
  Top Layer w0.5: U2.6 51.649,12.968 50.832,12.968 48.4,15.4 48.4,20.93 J5.3 50.63,24.9 52.007,24.9 52.3,25.193 52.3,26.207 52.007,26.5 50.993,26.5 50.7,26.793 50.7,27.8 51.224,28.324 U1.11 ; J15.10@61.467,28.322 J15.10
  Bottom Layer w0.6: U1.11@56.77,28.322 J15.10@61.467,28.322
R12_2: Q3.2 R12.2 | length 1.9
  Top Layer w0.8: Q3.2 74.237,39.612 74.237,41.521 R12.2
RST/P5.4: J14.7 U1.7 | length 4.9
  Top Layer w0.6: J14.7 36.456,35.948 41.331,35.948 U1.7
SW3_1: D1.1 D2.1 D3.1 SW3.1 SW3.2 SW4.1 SW4.2 SW5.1 SW5.2 | length 47.6
  Top Layer w0.6: D3.1 9.038,13.338 7.6,11.9 7.6,7.599 SW4.1 SW4.2 SW5.1 ; SW5.2 25.696,7.246 D1.1 25.759,13.271 31.9,13.271 ; D2.1 33.479,13.271 31.9,13.271 ; SW3.2 SW3.1 31.9,16.137 31.9,13.271
T: J5.2 J15.9 U1.12 U2.7 U7.1 | length 75.5
  Top Layer w0.3: U7.1 15.764,30.936 15.8,30.9
  Top Layer w0.4: 15.8,30.9 15.9,30.8 21.4,30.8 27.8,24.4 44,24.4 50.463,30.863 U1.12
  Top Layer w0.5: U2.7 51.649,14.238 50.862,14.238 49.3,15.8 49.3,20.97 50.07,21.74 J5.2 54.77,26.5 57.2,26.5 58.3,27.6 58.3,30.8 ; U1.12 U1.12@56.77,30.862 ; J15.9 J15.9
  Top Layer w0.6: U1.12@56.77,30.862 J15.9
U2_8: C6.1 U2.8 | length 2.4
  Top Layer w0.5: U2.8 51.677,15.48 53.52,15.48 C6.1
U6_1: R11.1 U6.1 | length 9.8
  Top Layer w0.6: R11.1 17.866,61.266 19.9,63.3 21.979,63.3 23.199,62.081 23.602,62.081 23.622,62.061 U6.1
U6_4: R10.1 U6.4 | length 8.2
  Top Layer w0.6: R10.1 20.029,49.629 21.082,50.682 U6.4
U7_2: LED4.2 R5.2 U7.2 | length 10.1
  Top Layer w0.3: R5.2 13.603,29.753 13.603,30.097 12.465,31.235 12.465,31.73 LED4.2 12.065,33.224 12.241,33.4 16.088,33.4 16.264,33.224 U7.2
U7_3: LED4.1 R6.1 U7.3 | length 12.9
  Top Layer w0.3: R6.1 11.782,29.747 11.782,30.218 10.865,31.135 10.865,31.73 LED4.1 10.465,33.365 11.1,34 16.4,34 16.764,33.636 U7.3
U7_7: LED5.2 R8.1 U7.7 | length 12.4
  Top Layer w0.3: 17.2,41.8 17.264,41.736 U7.7
  Top Layer w0.4: R8.1 13.158,41.524 13.525,41.891 13.647,41.891 14.156,42.4 16.6,42.4 17.2,41.8
  Top Layer w0.6: R8.1 13.162,41.399 13.162,39.246 LED5.2
U7_8: LED4.3 R7.1 U7.8 | length 12.1
  Top Layer w0.3: LED4.3 LED4.3@13.735,32.2 ; 16.7,38.8 16.764,38.736 U7.8
  Top Layer w0.4: R7.1 16.461,39.039 16.7,38.8
  Top Layer w0.6: LED4.3@13.735,32.2 v1(14.7,32.2) ; v1(15,37.9) 15,38.772 15.266,39.039 R7.1
  Bottom Layer w0.3: v1(14.7,32.2) 15,32.5 v1(15,37.9)
VCC: C1.1 C8.2 C9.2 C10.2 J5.1 J10.2 J13.1 J14.8 LED2.1 LED6.2 MPU6050.1 OLED1.2 OLED2.2 Q3.1 R5.1 R6.2 R7.2 R8.2 SW7.4 U1.8 U3.3 U5.3 U6.6 U7.10 | length 298.8
  Top Layer w0.3: U7.10 v2@15.764,37.7
  Top Layer w0.5: R6.2 10.576,29.021 10.576,28.224 11,27.8 15.2,27.8 15.636,28.236 15.636,29.021 R5.1 v1(16.747,29.337)
  Top Layer w0.8: LED6.2 9.533,51.669 9.233,51.969 9.233,52.469 6.9,54.802 6.9,56.3 ; v1(11.3,42.2) 13.5,44.4 23.6,44.4 ; OLED2.2 42.921,88.226 46.74,92.045 OLED1.2 46.724,92.25 46.724,93.376 46,94.1 39.3,94.1 38.639,93.439 38.639,92.239 C10.2 36.5,92.1 34.5,94.1 18.6,94.1 9.525,85.025 J10.2 9.353,80.092 7.592,80.092 6.9,79.4 6.9,56.3 ; v1(45.7,33.4) 44.094,33.4 44.06,33.367 41.387,33.367 U1.8 41.331,33.408 36.456,33.408 J14.8 34.599,33.401 23.6,44.4 ; J5.1 52.61,19.29 54.4,17.5 60.3,17.5 62.981,14.819 C1.1 ; SW7.4 63.019,6.997 63.019,11.011 C1.1 ; 68.248,11.1 68.248,21.248 68.717,21.717 LED2.1 70.162,39.7 ; U3.3@71.8,11.049 C1.1 ; Q3.1 70.259,39.604 70.162,39.7 ; v1(73.3,45.7) 70.162,42.562 70.162,39.7 ; v1(76.2,51.273) U5.3 76.28,56.214 76.28,57.48 77.3,58.5 82.8,58.5 86.233,55.067 MPU6050.1 ; 6.9,56.3 6.988,56.388 J13.1 18.688,56.388 19.4,57.1 23.131,57.1 23.6,56.631 23.6,55.437 23.6,44.4
  Bottom Layer w0.5: v1(11.3,42.2) 14.362,42.2 v1(16.057,40.505) 15.8,40.248 v2(15.8,37.7) 15.8,36.364 16.747,35.417 v1(16.747,29.337)
  Bottom Layer w0.8: v1(45.7,33.4) 47.1,32 47.1,27.31 J5.1 ; v1(73.3,45.7) 76.2,48.6 v1(76.2,51.273)
VIN: C7.2 J1.1 SW7.6 U2.5 USB1.1 | length 43.8
  Top Layer w0.4: USB1.1 47.595,5.3 ; 49.6,1.8 47.9,3.5 ; 47.595,5.3 47.595,3.405 49.3,1.7 49.7,1.7 47.9,3.5 ; 47.595,5.3 47.666,5.3 47.9,5.066 47.9,3.5
  Top Layer w0.6: 49.6,1.8 53,1.8 ; C7.2 51.6,9.3 51.975,8.925 51.975,8.151 52.326,7.8 53.2,7.8 54,7 54,2.8 53,1.8 ; C7.2@51.616,9.346 U2.5@51.616,11.638 ; SW7.6 61.726,0.6 54.2,0.6 53,1.8
  Top Layer w0.8: C7.2 C7.2@51.616,9.346 ; SW7.6 65.138,1.945 65.559,1.524 J1.1
pads on no net: OLED2. U2.4 U4.17 U4.18 USB1.6 USB1.7 USB1.8 USB1.9

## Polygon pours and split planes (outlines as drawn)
GND on Bottom Layer "NONET_L-01_P-001" (solid, remove dead copper, pour order 3): 0,98 0,0 98,0 98,98
BGND on Bottom Layer "NONET_L-01_P-001" (solid, remove dead copper, pour order 0): 43.9,16.4 43.9,1.5 52.8,1.5 54,0.3 72.2,0.3 72.2,2.1 70.8,3.5 66,3.5 64.5,5 64.5,7.7 62.8,9.4 58,9.4 55.9,11.5 55.9,15.3 54.8,16.4
LGND on Top Layer "NONET_L-01_P-001" (solid, remove dead copper, pour order 1): 6.5,54.7

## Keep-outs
Keep-Out Layer:
  the board outline again, w0.2

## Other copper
Bottom Layer:
  rectangle net LGND: 6.5,44.7 11.4,53.3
